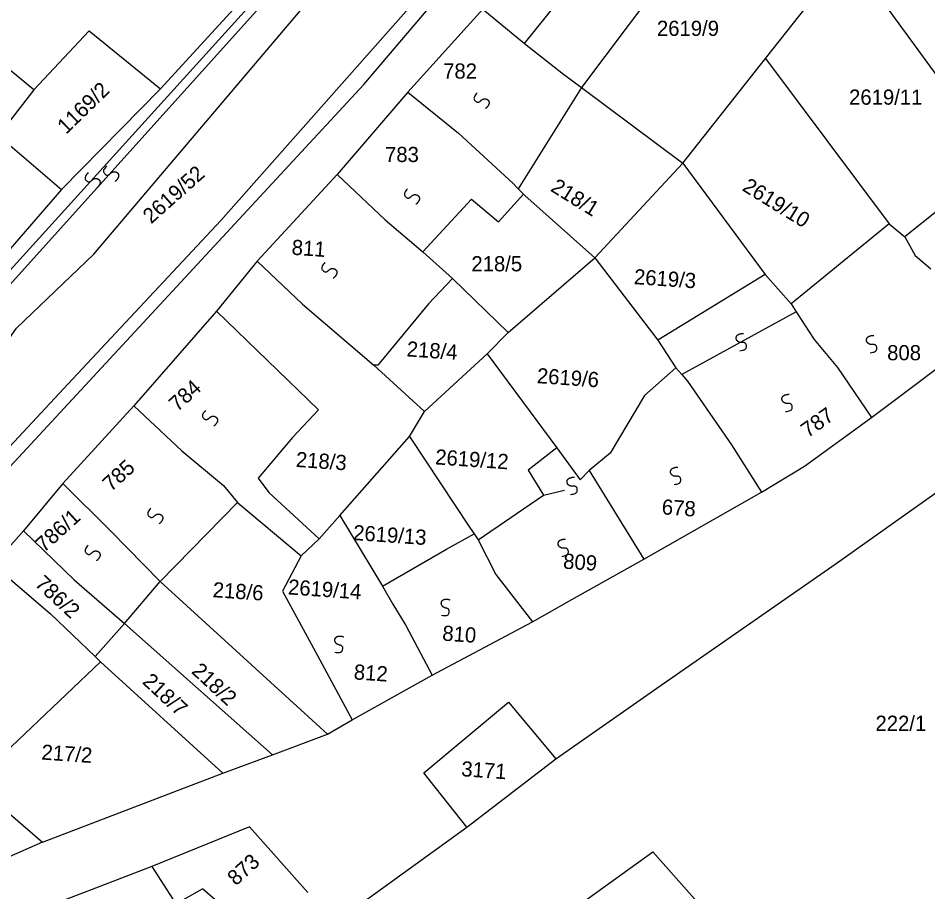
# Model space of a CAD drawing. Extents: x -581999 to -572728, y -1219553 to -1212032.
# Drawn here: x -577228 to -577108.1, y -1215413.6 to -1215298.5 of the extents above; entities that cross this region are included whole.
import ezdxf

# ---------------------------------------------------------------- set-up
doc = ezdxf.new("R2010")
doc.units = 0
for name, color, linetype in [('Vrstva 1', 7, 'Continuous'), ('Vrstva 2', 7, 'Continuous'), ('Vrstva 4', 7, 'Continuous'), ('Vrstva 6', 7, 'Continuous')]:
    doc.layers.add(name, color=color, linetype=linetype)

msp = doc.modelspace()

# ---------------------------------------------------------------- linework, layer by layer
at = {"layer": 'Vrstva 1'}
for p, q in [((-577129.473, -1215303.844), (-577118.578, -1215290.084)), ((-577217.998, -1215329.617), (-577186.261, -1215292.176)), ((-577140.369, -1215317.603), (-577129.473, -1215303.844)), ((-577169.908, -1215313.67), (-577162.734, -1215320.321)), ((-577162.734, -1215320.321), (-577162.051, -1215321.021)), ((-577162.051, -1215321.021), (-577161.37, -1215321.721)), ((-577141.277, -1215344.602), (-577140.51, -1215345.476)), ((-577140.51, -1215345.476), (-577139.743, -1215346.351)), ((-577139.743, -1215346.351), (-577133.96, -1215354.73)), ((-577213.925, -1215378.284), (-577217.797, -1215382.6)), ((-577233.872, -1215399.234), (-577217.09, -1215383.322)), ((-577224.735, -1215407.064), (-577234.559, -1215411.368))]:
    msp.add_line(p, q, dxfattribs=at)
for points in [[(-577068.022, -1215163.106), (-577076.012, -1215171.394), (-577092.817, -1215198.932), (-577107.282, -1215215.508), (-577162.965, -1215281.857), (-577201.26, -1215325.168), (-577221.372, -1215346.69), (-577272.951, -1215402.049), (-577277.91, -1215407.931), (-577301.723, -1215433.783), (-577314.534, -1215448.22), (-577343.272, -1215476.19), (-577359.94, -1215491.697), (-577381.842, -1215506.802), (-577421.443, -1215531.966), (-577436.182, -1215542.126), (-577449.269, -1215550.815), (-577464.697, -1215563.514), (-577494.524, -1215587.485), (-577505.622, -1215596.863)], [(-577189.463, -1215286.257), (-577209.205, -1215307.84)], [(-577118.578, -1215290.084), (-577098.683, -1215317.344)], [(-577148.284, -1215292.019), (-577144.353, -1215295.172), (-577153.716, -1215307.66)], [(-577166.722, -1215297.339), (-577176.589, -1215308.258)], [(-577166.722, -1215297.339), (-577161.237, -1215301.876)], [(-577225.896, -1215307.952), (-577237.114, -1215298.724)], [(-577225.896, -1215307.952), (-577218.62, -1215300.191)], [(-577218.62, -1215300.191), (-577209.205, -1215307.84)], [(-577161.237, -1215301.876), (-577156.109, -1215305.907)], [(-577129.473, -1215303.844), (-577113.152, -1215325.601)], [(-577156.109, -1215305.907), (-577153.716, -1215307.66)], [(-577225.896, -1215307.952), (-577230.579, -1215313.979)], [(-577209.205, -1215307.84), (-577222.241, -1215321.075)], [(-577153.716, -1215307.66), (-577162.051, -1215321.021)], [(-577153.716, -1215307.66), (-577140.369, -1215317.603)], [(-577176.589, -1215308.258), (-577185.912, -1215319.114)], [(-577176.589, -1215308.258), (-577169.908, -1215313.67)], [(-577230.579, -1215313.979), (-577222.241, -1215321.075)], [(-577151.962, -1215330.077), (-577140.369, -1215317.603)], [(-577140.369, -1215317.603), (-577129.514, -1215332.305)], [(-577098.683, -1215317.344), (-577111.103, -1215327.351)], [(-577185.912, -1215319.114), (-577196.47, -1215330.55)], [(-577185.912, -1215319.114), (-577179.606, -1215325.111)], [(-577222.241, -1215321.075), (-577234.131, -1215334.731)], [(-577174.65, -1215329.313), (-577168.233, -1215322.37)], [(-577168.233, -1215322.37), (-577164.644, -1215325.347)], [(-577161.37, -1215321.721), (-577164.644, -1215325.347)], [(-577161.37, -1215321.721), (-577161.185, -1215321.883), (-577151.962, -1215330.077)], [(-577179.606, -1215325.111), (-577174.65, -1215329.313)], [(-577113.152, -1215325.601), (-577126.105, -1215336.15)], [(-577113.152, -1215325.601), (-577111.103, -1215327.351)], [(-577111.103, -1215327.351), (-577109.746, -1215329.794)], [(-577230.947, -1215343.252), (-577228.161, -1215339.371), (-577217.998, -1215329.617)], [(-577174.65, -1215329.313), (-577170.721, -1215332.814)], [(-577109.746, -1215329.794), (-577107.697, -1215331.545)], [(-577196.47, -1215330.55), (-577201.841, -1215337.138)], [(-577196.47, -1215330.55), (-577190.506, -1215336.197)], [(-577163.367, -1215339.94), (-577151.962, -1215330.077)], [(-577151.962, -1215330.077), (-577143.657, -1215340.937)], [(-577170.721, -1215332.814), (-577173.888, -1215336.149)], [(-577170.721, -1215332.814), (-577163.367, -1215339.94)], [(-577129.514, -1215332.305), (-577143.657, -1215340.937)], [(-577129.514, -1215332.305), (-577126.105, -1215336.15)], [(-577190.506, -1215336.197), (-577181.107, -1215344.25)], [(-577173.888, -1215336.149), (-577180.577, -1215344.24), (-577181.107, -1215344.25)], [(-577126.105, -1215336.15), (-577125.425, -1215337.198)], [(-577201.841, -1215337.138), (-577212.736, -1215349.593)], [(-577201.841, -1215337.138), (-577188.363, -1215350.132), (-577191.823, -1215353.77)], [(-577125.425, -1215337.198), (-577123.045, -1215340.864)], [(-577166.173, -1215342.74), (-577163.367, -1215339.94)], [(-577115.516, -1215351.134), (-577101.211, -1215340.437)], [(-577143.657, -1215340.937), (-577141.277, -1215344.602)], [(-577123.045, -1215340.864), (-577119.979, -1215344.533)], [(-577174.432, -1215350.327), (-577166.173, -1215342.74)], [(-577166.173, -1215342.74), (-577156.979, -1215355.14)], [(-577181.107, -1215344.25), (-577174.432, -1215350.327)], [(-577141.277, -1215344.602), (-577145.409, -1215348.216)], [(-577119.979, -1215344.533), (-577115.516, -1215351.134)], [(-577157.089, -1215396.109), (-577143.803, -1215386.778), (-577120.166, -1215370.366), (-577098.252, -1215354.816), (-577087.731, -1215347.736)], [(-577145.409, -1215348.216), (-577149.927, -1215355.85)], [(-577212.736, -1215349.593), (-577222.082, -1215359.816)], [(-577212.736, -1215349.593), (-577206.39, -1215355.523)], [(-577176.382, -1215353.654), (-577174.432, -1215350.327)], [(-577124.318, -1215357.528), (-577115.516, -1215351.134)], [(-577191.823, -1215353.77), (-577196.326, -1215359.143), (-577194.905, -1215361.032)], [(-577185.557, -1215364.05), (-577176.382, -1215353.654)], [(-577176.382, -1215353.654), (-577168.387, -1215365.699), (-577167.87, -1215366.474)], [(-577133.96, -1215354.73), (-577130.008, -1215360.98)], [(-577206.39, -1215355.523), (-577200.919, -1215360.074)], [(-577156.979, -1215355.14), (-577160.763, -1215358.059), (-577158.724, -1215361.375)], [(-577156.979, -1215355.14), (-577153.915, -1215359.331)], [(-577149.927, -1215355.85), (-577152.705, -1215358.119)], [(-577153.915, -1215359.331), (-577152.705, -1215358.119)], [(-577152.705, -1215358.119), (-577145.525, -1215369.778)], [(-577130.008, -1215360.98), (-577124.318, -1215357.528)], [(-577222.082, -1215359.816), (-577227.279, -1215366.057)], [(-577222.082, -1215359.816), (-577215.738, -1215366.094)], [(-577200.919, -1215360.074), (-577199.043, -1215362.346)], [(-577194.905, -1215361.032), (-577188.288, -1215367.14)], [(-577167.353, -1215367.25), (-577158.724, -1215361.375)], [(-577145.525, -1215369.778), (-577130.008, -1215360.98)], [(-577209.249, -1215372.738), (-577199.043, -1215362.346)], [(-577199.043, -1215362.346), (-577190.669, -1215369.346)], [(-577188.288, -1215367.14), (-577185.557, -1215364.05)], [(-577185.557, -1215364.05), (-577179.934, -1215373.352)], [(-577227.279, -1215366.057), (-577231.261, -1215370.563)], [(-577227.279, -1215366.057), (-577220.592, -1215372.51)], [(-577215.738, -1215366.094), (-577209.249, -1215372.738)], [(-577171.493, -1215368.461), (-577167.87, -1215366.474)], [(-577167.87, -1215366.474), (-577167.353, -1215367.25)], [(-577190.669, -1215369.346), (-577188.288, -1215367.14)], [(-577167.353, -1215367.25), (-577164.992, -1215371.804)], [(-577190.669, -1215369.346), (-577193.105, -1215374.033), (-577188.514, -1215382.49)], [(-577179.934, -1215373.352), (-577171.493, -1215368.461)], [(-577231.261, -1215370.563), (-577223.714, -1215377.02)], [(-577155.007, -1215375.125), (-577145.525, -1215369.778)], [(-577220.592, -1215372.51), (-577213.925, -1215378.284)], [(-577213.925, -1215378.284), (-577209.249, -1215372.738)], [(-577209.249, -1215372.738), (-577187.201, -1215392.844)], [(-577164.992, -1215371.804), (-577160.179, -1215378.058)], [(-577179.934, -1215373.352), (-577178.589, -1215375.742)], [(-577160.179, -1215378.058), (-577155.007, -1215375.125)], [(-577178.589, -1215375.742), (-577176.871, -1215378.523)], [(-577223.714, -1215377.02), (-577217.797, -1215382.6), (-577217.09, -1215383.322), (-577200.978, -1215397.999)], [(-577213.925, -1215378.284), (-577194.434, -1215395.593)], [(-577176.871, -1215378.523), (-577173.406, -1215385.08)], [(-577173.406, -1215385.08), (-577160.179, -1215378.058)], [(-577188.514, -1215382.49), (-577183.924, -1215390.945)], [(-577183.924, -1215390.945), (-577173.406, -1215385.08)], [(-577246.787, -1215387.821), (-577238.723, -1215395.026), (-577233.872, -1215399.234), (-577224.735, -1215407.064)], [(-577168.829, -1215405.097), (-577174.505, -1215397.957), (-577163.334, -1215388.654), (-577157.089, -1215396.109)], [(-577187.201, -1215392.844), (-577183.924, -1215390.945)], [(-577194.434, -1215395.593), (-577187.201, -1215392.844)], [(-577200.978, -1215397.999), (-577194.434, -1215395.593)], [(-577168.829, -1215405.097), (-577157.089, -1215396.109)], [(-577224.735, -1215407.064), (-577200.978, -1215397.999)], [(-577189.793, -1215413.718), (-577197.465, -1215405.048), (-577210.36, -1215410.31)], [(-577182.464, -1215414.949), (-577168.829, -1215405.097)], [(-577153.88, -1215415.24), (-577144.322, -1215408.339), (-577138.176, -1215415.312)], [(-577210.36, -1215410.31), (-577244.205, -1215423.291)], [(-577210.36, -1215410.31), (-577207.202, -1215415.221), (-577203.648, -1215413.22)], [(-577197.707, -1215418.401), (-577203.648, -1215413.22)]]:
    msp.add_lwpolyline(points, dxfattribs=at)
at = {"layer": 'Vrstva 4'}
for p, q in [((-577182.387, -1215307.256), (-577132.562, -1215248.619)), ((-577234.361, -1215337.594), (-577188.743, -1215287.242)), ((-577233.254, -1215338.26), (-577188.079, -1215288.153)), ((-577276.658, -1215409.001), (-577182.387, -1215307.256))]:
    msp.add_line(p, q, dxfattribs=at)
for points in [[(-577161.237, -1215301.876), (-577154.18, -1215293.038), (-577150.431, -1215295.077), (-577148.284, -1215292.019)], [(-577125.425, -1215337.198), (-577140.51, -1215345.476)], [(-577158.724, -1215361.375), (-577155.972, -1215360.692)]]:
    msp.add_lwpolyline(points, dxfattribs=at)
at = {"layer": 'Vrstva 6'}
for points in [[(-577167.466, -1215308.374), (-577168.053, -1215308.996), (-577167.598, -1215309.605), (-577167.192, -1215309.593), (-577166.906, -1215309.288), (-577166.6, -1215309.134), (-577166.3, -1215309.15), (-577166.093, -1215309.252), (-577165.917, -1215309.455), (-577165.872, -1215309.819), (-577166.207, -1215310.331), (-577166.365, -1215310.423)], [(-577218.726, -1215318.867), (-577219.313, -1215319.489), (-577218.858, -1215320.098), (-577218.452, -1215320.086), (-577218.166, -1215319.781), (-577217.86, -1215319.627), (-577217.56, -1215319.643), (-577217.353, -1215319.745), (-577217.177, -1215319.948), (-577217.132, -1215320.312), (-577217.467, -1215320.824), (-577217.625, -1215320.916)], [(-577216.29, -1215317.979), (-577216.877, -1215318.601), (-577216.422, -1215319.21), (-577216.016, -1215319.198), (-577215.73, -1215318.893), (-577215.424, -1215318.739), (-577215.124, -1215318.755), (-577214.917, -1215318.857), (-577214.741, -1215319.06), (-577214.696, -1215319.424), (-577215.031, -1215319.936), (-577215.189, -1215320.028)], [(-577176.644, -1215320.998), (-577177.231, -1215321.62), (-577176.776, -1215322.229), (-577176.37, -1215322.217), (-577176.084, -1215321.912), (-577175.778, -1215321.758), (-577175.478, -1215321.774), (-577175.271, -1215321.876), (-577175.095, -1215322.079), (-577175.05, -1215322.443), (-577175.385, -1215322.955), (-577175.543, -1215323.047)], [(-577187.527, -1215330.729), (-577188.114, -1215331.351), (-577187.659, -1215331.96), (-577187.253, -1215331.948), (-577186.967, -1215331.643), (-577186.661, -1215331.489), (-577186.361, -1215331.505), (-577186.154, -1215331.607), (-577185.978, -1215331.81), (-577185.933, -1215332.174), (-577186.268, -1215332.686), (-577186.426, -1215332.778)], [(-577132.863, -1215342.335), (-577132.012, -1215342.246), (-577131.96, -1215341.488), (-577132.276, -1215341.232), (-577132.692, -1215341.277), (-577133.024, -1215341.195), (-577133.241, -1215340.987), (-577133.332, -1215340.775), (-577133.333, -1215340.506), (-577133.13, -1215340.201), (-577132.542, -1215340.031), (-577132.362, -1215340.064)], [(-577115.687, -1215342.598), (-577114.836, -1215342.509), (-577114.784, -1215341.751), (-577115.1, -1215341.495), (-577115.516, -1215341.54), (-577115.848, -1215341.458), (-577116.065, -1215341.25), (-577116.156, -1215341.038), (-577116.157, -1215340.769), (-577115.954, -1215340.464), (-577115.366, -1215340.294), (-577115.186, -1215340.327)], [(-577126.832, -1215350.357), (-577125.981, -1215350.268), (-577125.929, -1215349.51), (-577126.245, -1215349.254), (-577126.661, -1215349.299), (-577126.993, -1215349.217), (-577127.21, -1215349.009), (-577127.301, -1215348.797), (-577127.302, -1215348.528), (-577127.099, -1215348.223), (-577126.511, -1215348.053), (-577126.331, -1215348.086)], [(-577203.26, -1215350.192), (-577203.847, -1215350.814), (-577203.392, -1215351.423), (-577202.986, -1215351.411), (-577202.7, -1215351.106), (-577202.394, -1215350.952), (-577202.094, -1215350.968), (-577201.887, -1215351.07), (-577201.711, -1215351.273), (-577201.666, -1215351.637), (-577202.001, -1215352.149), (-577202.159, -1215352.241)], [(-577141.517, -1215359.957), (-577140.666, -1215359.868), (-577140.614, -1215359.11), (-577140.93, -1215358.854), (-577141.346, -1215358.899), (-577141.678, -1215358.817), (-577141.895, -1215358.609), (-577141.986, -1215358.397), (-577141.987, -1215358.128), (-577141.784, -1215357.823), (-577141.196, -1215357.653), (-577141.016, -1215357.686)], [(-577155.153, -1215361.272), (-577154.302, -1215361.183), (-577154.25, -1215360.425), (-577154.566, -1215360.169), (-577154.982, -1215360.214), (-577155.314, -1215360.132), (-577155.531, -1215359.924), (-577155.622, -1215359.712), (-577155.623, -1215359.443), (-577155.42, -1215359.138), (-577154.832, -1215358.968), (-577154.652, -1215359.001)], [(-577210.471, -1215363.08), (-577211.058, -1215363.702), (-577210.603, -1215364.311), (-577210.197, -1215364.299), (-577209.911, -1215363.994), (-577209.605, -1215363.84), (-577209.305, -1215363.856), (-577209.098, -1215363.958), (-577208.922, -1215364.161), (-577208.877, -1215364.525), (-577209.212, -1215365.037), (-577209.37, -1215365.129)], [(-577218.731, -1215367.946), (-577219.318, -1215368.568), (-577218.863, -1215369.177), (-577218.457, -1215369.165), (-577218.171, -1215368.86), (-577217.865, -1215368.706), (-577217.565, -1215368.722), (-577217.358, -1215368.824), (-577217.182, -1215369.027), (-577217.137, -1215369.391), (-577217.472, -1215369.903), (-577217.63, -1215369.995)], [(-577156.333, -1215369.425), (-577155.482, -1215369.336), (-577155.43, -1215368.578), (-577155.746, -1215368.322), (-577156.162, -1215368.367), (-577156.494, -1215368.285), (-577156.711, -1215368.077), (-577156.802, -1215367.865), (-577156.803, -1215367.596), (-577156.6, -1215367.291), (-577156.012, -1215367.121), (-577155.832, -1215367.154)], [(-577172.189, -1215377.194), (-577171.348, -1215377.346), (-577171.085, -1215376.632), (-577171.317, -1215376.298), (-577171.729, -1215376.225), (-577172.025, -1215376.053), (-577172.175, -1215375.792), (-577172.203, -1215375.563), (-577172.129, -1215375.305), (-577171.848, -1215375.069), (-577171.236, -1215375.071), (-577171.073, -1215375.153)], [(-577186.218, -1215382.059), (-577185.377, -1215382.211), (-577185.114, -1215381.497), (-577185.346, -1215381.163), (-577185.758, -1215381.09), (-577186.054, -1215380.918), (-577186.204, -1215380.657), (-577186.232, -1215380.428), (-577186.158, -1215380.17), (-577185.877, -1215379.934), (-577185.265, -1215379.936), (-577185.102, -1215380.018)]]:
    msp.add_open_spline(points, degree=2, dxfattribs=at)

# ---------------------------------------------------------------- texts
at = {"layer": 'Vrstva 2'}
for s, p in [('2619/9', (-577143.779, -1215300.86)), ('782', (-577171.954, -1215306.484)), ('2619/11', (-577118.457, -1215309.921)), ('783', (-577179.612, -1215317.476)), ('218/5', (-577168.233, -1215331.875)), ('808', (-577113.438, -1215343.594)), ('222/1', (-577114.976, -1215392.418))]:
    msp.add_text(s, height=2, dxfattribs=at).set_placement(p)
for s, rotation, p in [('1169/2', 44.13117, (-577221.632, -1215313.882)), ('2619/52', 41.64703, (-577210.429, -1215325.691)), ('218/1', 328.31169, (-577157.924, -1215321.215)), ('2619/10', 328.31169, (-577132.665, -1215321.147)), ('811', 356.03802, (-577191.965, -1215329.681)), ('2619/3', 356.03802, (-577146.855, -1215333.555)), ('218/4', 356.03802, (-577176.804, -1215343.074)), ('2619/6', 356.03802, (-577159.648, -1215346.6)), ('784', 42.16454, (-577206.967, -1215350.455)), ('787', 35.33464, (-577123.895, -1215353.872)), ('218/3', 356.03802, (-577191.414, -1215357.637)), ('2619/12', 356.03802, (-577173.047, -1215357.302)), ('785', 42.16454, (-577215.714, -1215360.982)), ('678', 356.03802, (-577143.188, -1215363.882)), ('786/1', 42.16454, (-577224.555, -1215368.986)), ('2619/13', 356.03802, (-577183.867, -1215367.272)), ('809', 356.03802, (-577156.187, -1215371.033)), ('786/2', 317.23438, (-577225.893, -1215373.211)), ('218/6', 356.03802, (-577202.371, -1215374.801)), ('2619/14', 356.03802, (-577192.443, -1215374.437)), ('810', 356.03802, (-577172.115, -1215380.52)), ('218/2', 317.23438, (-577205.236, -1215384.707)), ('812', 356.03802, (-577183.779, -1215385.627)), ('218/7', 317.23438, (-577211.713, -1215386.086)), ('217/2', 356.03802, (-577224.939, -1215396.194)), ('3171', 356.03802, (-577169.609, -1215398.388)), ('873', 42.16454, (-577199.271, -1215412.912))]:
    msp.add_text(s, height=2, rotation=rotation, dxfattribs=at).set_placement(p)

doc.saveas('drawing.dxf')
